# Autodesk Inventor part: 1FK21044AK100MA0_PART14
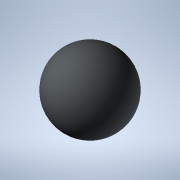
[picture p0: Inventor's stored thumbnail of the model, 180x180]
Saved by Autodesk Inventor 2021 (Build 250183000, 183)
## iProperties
Created: 2025-04
Part Number: 1FK21044AK100MA0_PART14
Material: Generic
Catalog Web Link: www.3dfindit.com
Description: -Servo synchronous motor
Document SubType Name: Modeling
Designer: psAdmin
Mass: 0.137258 g
Surface Area: 1.2868 cm^2
Volume: 0.137258 cm^3
Density: 1 g/cm^3
Appearance: PSOLRGB-212-217-219
Category: PARTsolutions
Title: 1FK21044AK100MA0_PART14
Author: Cadenas PARTsolutions
Comments: Servo synchronous motor
Sending System: PARTsolutions
Preprocessor: ST-DEVELOPER v19.3
PSOL_IDENT_0: {$CADENAS_DATA/23d-libs/siemens_ag/_cat_/5e/d8/1fk21044ak100ma0.prj},216 {VTYP=3D},{NB=1FK21044AK100
PSOL_IDENT_1: MA0_PART14},{LINA=1FK21044AK100MA0_PART14},{NN=1FK21044AK100MA0_PART14},{NOPRJ=TRUE},{DATE=19.08.202
PSOL_IDENT_2: 5 14:00:41},{GEOMDATE=30.07.2025 02:00:53},{VERSION=},{LINEID=10},{WBVAR=},{WBNUMERIC=}  {NB=1FK2104
PSOL_IDENT_3: 4AK100MA0_PART14},{LINA=1FK21044AK100MA0_PART14},{KT=DUMMY},{PREVIEW=../../../_pool_/cb/72/p_d211_xx
PSOL_IDENT_4: _00434j.png},{DESCSHORT=SIMOTICS S-1FK2 HD, SINAMICS S210 3AC 400V-480V, 0.95 Nm, 6000 rpm},{DESCLON
PSOL_IDENT_5: G=SIMOTICS S-1FK2 HD servo motor M0=1.27 Nm; PN = 0.6 kW at nN=6000 rpm (380-480 V); PN = 0.4 kW at
PSOL_IDENT_6: nN=3000 rpm (200-240 V); with holding brake; degree of protection IP64; cylindrical shaft D19x40mm;
PSOL_IDENT_7: absolute encoder 22-bit + 12-bit multiturn (encoder AM22DQC); with OCC interface; plug size M17, rot
PSOL_IDENT_8: atable; SIMOTICS S-1FK2 servomotorfor a wide range of uses in industrial environments. SIMOTICS S‑1F
PSOL_IDENT_9: K2 servomotors are compact synchronous motors with a high dynamic performance that set themselves ap
PSOL_IDENT_10: art as a result of their high power density, degree of protection and overload capability. The motor
PSOL_IDENT_11: s are available in two variants: as High Dynamic variant (highest dynamic performance as a result of
PSOL_IDENT_12: the low intrinsic moment of inertia for applications demanding a high dynamic performance with low
PSOL_IDENT_13: moved masses) - and as Compact variant (precise and stable closed-loop control for medium up to larg
PSOL_IDENT_14: e moved masses as a result of a medium intrinsic moment of inertia). SIMOTICSS‑1FK2 servomotors full
PSOL_IDENT_15: y exploit their strengths in a system with the SINAMICSS210 frequency converter and simple connectio
PSOL_IDENT_16: n using the one cable connection (OCC). Advantages include the short control and positioning times,
PSOL_IDENT_17: fast and precise correction of disturbing quantities as well as stable control with a high dynamic p
PSOL_IDENT_18: erformance. The servo motors can be configured to address a wide range of requirements. For example
PSOL_IDENT_19: with and without holding brake, IP64 or IP65 degree of protection, singleturn or multiturn absolute
PSOL_IDENT_20: encoders - to name just a few. Further, the servomotors are available in different shaft heights ext
PSOL_IDENT_21: ending from 20 to 100. A shaft sealing ring is available to achieve an IP65 degree of protection and
PSOL_IDENT_22: for subsequent mounting at the motor or as spare part. SIMOTICS - the optimum motor for each and ev
PSOL_IDENT_23: ery motion control application.},{INTNO=804766910005},{SUPPLIERALTNO=1FK2104-4AK10-0MA0},{MANUID=1FK
PSOL_IDENT_24: 21044AK100MA0},{MANUNAME=Siemens},{MANUTYPEDESC=Synchronous motor 1FK2-HD 1,27 Nm},{AAU732=SIMOTICS}
PSOL_IDENT_25: ,{AAO057=S-1FK2},{AAU734=SIMOTICS S-1FK2 HD servo motor M0=1.27 Nm; PN = 0.6 kW at nN=6000 rpm (380-
PSOL_IDENT_26: 480 V); PN = 0.4 kW at nN=3000 rpm (200-240 V); with holding brake; degree of protection IP64; cylin
PSOL_IDENT_27: drical shaft D19x40mm; absolute encoder 22-bit + 12-bit multiturn (encoder AM22DQC); with OCC interf
PSOL_IDENT_28: ace; plug size M17, rotatable;},{AAW338=Synchronous motor 1FK2-HD 1,27 Nm},{AAO742=SIMOTICS},{AAO663=
PSOL_IDENT_29: 4042948691076},{NOCUPEROU=1},{PRICEQUANTITY=1},{QUANTITYMIN=1},{QUANTITYINT=1},{CTN=85015100},{COO=D
PSOL_IDENT_30: E},{AAO676=1FK2104-4AK10-0MA0},{AAO677=Siemens AG},{ORDERUNIT=C62},{CONTENTUNIT=C62}
NB: 1FK21044AK100MA0_PART14
NT: Servo synchronous motor
NBSYN: $MANUID._PART14
LINA: 1FK21044AK100MA0_PART14
CATALOG: SIEMENS
PREVIEW: ../../../_pool_/cb/72/p_d211_xx_00434j.png
DESCSHORT: SIMOTICS S-1FK2 HD, SINAMICS S210 3AC 400V-480V, 0.95 Nm, 6000 rpm
DESCLONG: SIMOTICS S-1FK2 HD servo motor M0=1.27 Nm; PN = 0.6 kW at nN=6000 rpm (380-480 V); PN = 0.4 kW at nN=3000 rpm (200-240 V); with holding brake; degree of protect
INTNO: 804766910005
SUPPLIERALTNO: 1FK2104-4AK10-0MA0
MANUID: 1FK21044AK100MA0
MANUNAME: Siemens
MANUTYPEDESC: Synchronous motor 1FK2-HD 1,27 Nm
AAU732: SIMOTICS
AAO057: S-1FK2
AAU734: SIMOTICS S-1FK2 HD servo motor M0=1.27 Nm; PN = 0.6 kW at nN=6000 rpm (380-480 V); PN = 0.4 kW at nN=3000 rpm (200-240 V); with holding brake; degree of protect
AAW338: Synchronous motor 1FK2-HD 1,27 Nm
AAO742: SIMOTICS
AAO663: 4042948691076.0
NOCUPEROU: 1
PRICEQUANTITY: 1
QUANTITYMIN: 1
QUANTITYINT: 1
CTN: 85015100
COO: DE
ARTICLENO: 1FK21044AK100MA0_PART14
BOMINFO: 1FK21044AK100MA0_PART14
CREATOR: CADENAS GmbH
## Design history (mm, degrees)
feature "2025_04_17_15_35_41_0968"
body "Solid1"
